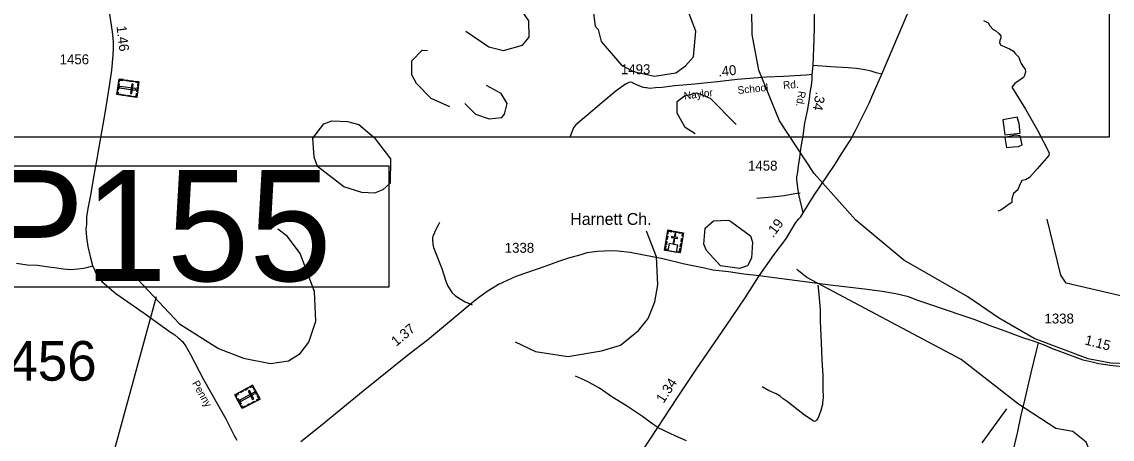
# Model space of a CAD drawing. Extents: x 2093524 to 2270757, y 289120 to 570408.
# Drawn here: x 2149214 to 2162986, y 498150 to 503417 of the extents above; entities that cross this region are included whole.
import ezdxf

# ---------------------------------------------------------------- set-up
doc = ezdxf.new("R2010")
doc.units = 0
for name, color, linetype in [('Exist Cultural Cemetery CELL', 7, 'Continuous'), ('Exist Cultural Church with Cemetery CELL', 7, 'Continuous'), ('Exist Cultural Church with Cemetery Label', 7, 'Continuous'), ('Exist Hydrographic Creek Single Shore', 7, 'Continuous'), ('Exist Hydrographic Lagoon', 7, 'Continuous'), ('Exist Hydrographic Misc Water Feature', 7, 'Continuous'), ('Exist Hydrographic Pond Under 1500 Sq Ft', 7, 'Continuous'), ('Exist Road Non-System Type 51', 7, 'Continuous'), ('Exist Road Primary NC Attributed', 7, 'Continuous'), ('Exist Road Primary NC Mileage Hundredths English Label', 7, 'Continuous'), ('Exist Road Secondary Mileage Hundredths English Label', 7, 'Continuous'), ('Exist Road Secondary Structure Pipe Number Label', 7, 'Continuous'), ('Exist Road Secondary Type 51 Attributed', 7, 'Continuous'), ('Exist Road Secondary Type 51 Label', 7, 'Continuous'), ('Exist Road Secondary Type 51 Number Label', 7, 'Continuous'), ('Map Preparation Inset Cut Line', 7, 'Continuous')]:
    doc.layers.add(name, color=color, linetype=linetype)

msp = doc.modelspace()

# ---------------------------------------------------------------- linework, layer by layer
at = {"layer": 'Exist Cultural Cemetery CELL'}
for points in [[(2150694, 502659), (2150666, 502462), (2150414, 502498), (2150442, 502695)], [(2150437, 502662), (2150449, 502661), (2150452, 502682), (2150492, 502677), (2150493, 502688), (2150442, 502695)], [(2150445, 502636), (2150433, 502552), (2150422, 502554), (2150434, 502638)], [(2150650, 502555), (2150652, 502574), (2150452, 502602), (2150449, 502584)], [(2150511, 502685), (2150554, 502679), (2150552, 502668), (2150510, 502674)], [(2150578, 502676), (2150621, 502670), (2150619, 502658), (2150576, 502664)], [(2150621, 502628), (2150602, 502631), (2150586, 502514), (2150604, 502512)], [(2150651, 502665), (2150650, 502654), (2150681, 502650), (2150676, 502609), (2150687, 502608), (2150694, 502659)], [(2150684, 502586), (2150676, 502535), (2150665, 502536), (2150672, 502587)], [(2150419, 502531), (2150430, 502529), (2150427, 502507), (2150467, 502502), (2150465, 502491), (2150414, 502498)], [(2150487, 502499), (2150530, 502493), (2150528, 502482), (2150485, 502488)], [(2150552, 502490), (2150595, 502484), (2150594, 502472), (2150551, 502478)], [(2150623, 502468), (2150625, 502479), (2150657, 502475), (2150662, 502515), (2150673, 502513), (2150666, 502462)], [(2152129, 498831), (2152224, 498656), (2151999, 498535), (2151905, 498710)], [(2151921, 498681), (2151931, 498687), (2151921, 498706), (2151956, 498725), (2151951, 498735), (2151905, 498710)], [(2151967, 498743), (2152005, 498764), (2152010, 498754), (2151972, 498733)], [(2152155, 498721), (2152146, 498737), (2151968, 498641), (2151977, 498625)], [(2152026, 498775), (2152064, 498796), (2152070, 498786), (2152031, 498765)], [(2152089, 498763), (2152072, 498754), (2152128, 498650), (2152145, 498659)], [(2152091, 498810), (2152097, 498800), (2152125, 498816), (2152144, 498780), (2152154, 498785), (2152129, 498831)], [(2152165, 498766), (2152189, 498720), (2152179, 498715), (2152154, 498760)], [(2152186, 498635), (2152180, 498645), (2152209, 498660), (2152189, 498696), (2152199, 498701), (2152224, 498655)], [(2151943, 498665), (2151983, 498590), (2151973, 498585), (2151932, 498660)], [(2151984, 498564), (2151994, 498570), (2152004, 498550), (2152040, 498569), (2152045, 498560), (2151999, 498535)], [(2152058, 498579), (2152096, 498600), (2152101, 498590), (2152063, 498569)], [(2152116, 498610), (2152154, 498631), (2152159, 498621), (2152121, 498600)]]:
    msp.add_lwpolyline(points, close=True, dxfattribs=at)
at = {"layer": 'Exist Cultural Church with Cemetery CELL'}
for points in [[(2157375, 500787), (2157571, 500754), (2157529, 500503), (2157332, 500536)], [(2157368, 500744), (2157379, 500743), (2157384, 500774), (2157424, 500768), (2157426, 500778), (2157375, 500787)], [(2157448, 500775), (2157499, 500766), (2157497, 500755), (2157446, 500764)], [(2157564, 500711), (2157553, 500713), (2157558, 500745), (2157518, 500751), (2157520, 500762), (2157571, 500754)], [(2157344, 500605), (2157351, 500648), (2157362, 500646), (2157355, 500603)], [(2157355, 500671), (2157362, 500714), (2157374, 500712), (2157366, 500669)], [(2157375, 500529), (2157485, 500510), (2157501, 500599), (2157450, 500608), (2157464, 500688), (2157497, 500683), (2157498, 500694), (2157466, 500699), (2157473, 500741), (2157462, 500743), (2157454, 500701), (2157422, 500707), (2157420, 500696), (2157453, 500690), (2157439, 500610), (2157390, 500618)], [(2157541, 500641), (2157548, 500684), (2157559, 500682), (2157552, 500639)], [(2157365, 500531), (2157367, 500542), (2157345, 500546), (2157352, 500585), (2157341, 500587), (2157332, 500536)], [(2157496, 500508), (2157498, 500520), (2157520, 500516), (2157526, 500556), (2157537, 500554), (2157529, 500503)], [(2157529, 500576), (2157537, 500619), (2157548, 500617), (2157541, 500574)]]:
    msp.add_lwpolyline(points, close=True, dxfattribs=at)
at = {"layer": 'Exist Hydrographic Creek Single Shore'}
msp.add_lwpolyline([(2161363, 503435), (2161419, 503402), (2161442, 503364), (2161482, 503318), (2161516, 503301), (2161553, 503269), (2161582, 503239), (2161582, 503210), (2161566, 503179), (2161563, 503152), (2161582, 503122), (2161592, 503116), (2161630, 503099), (2161689, 503076), (2161739, 503045), (2161756, 503022), (2161807, 502969), (2161823, 502920), (2161836, 502890), (2161867, 502846), (2161886, 502817), (2161890, 502783), (2161878, 502739), (2161868, 502712), (2161756, 502638), (2161717, 502591), (2161768, 502511), (2161892, 502316), (2162043, 502049), (2162192, 501762), (2162187, 501728), (2162038, 501562), (2161944, 501450), (2161892, 501423), (2161846, 501416), (2161812, 501343), (2161793, 501297), (2161739, 501251), (2161717, 501182), (2161717, 501136), (2161686, 501117), (2161637, 501083), (2161579, 501041), (2161544, 501029)], dxfattribs=at)
at = {"layer": 'Exist Hydrographic Lagoon'}
for points in [[(2161605, 502180), (2161630, 501990), (2161824, 502012), (2161810, 502132), (2161785, 502212)], [(2161632, 501956), (2161652, 501830), (2161737, 501839), (2161802, 501844), (2161851, 501864), (2161824, 501978), (2161759, 501986)]]:
    msp.add_lwpolyline(points, close=True, dxfattribs=at)
at = {"layer": 'Exist Hydrographic Misc Water Feature'}
for points in [[(2159750, 500914), (2159221, 501502), (2158785, 502167), (2158523, 502805), (2158437, 503256), (2158435, 503571), (2158492, 503839), (2158599, 504122), (2159038, 504583), (2159328, 504760)], [(2154821, 503299), (2155114, 503103), (2155297, 503054), (2155539, 503121), (2155621, 503221), (2155620, 503431), (2155478, 503631), (2155152, 503729), (2154936, 503717)], [(2154619, 502342), (2154385, 502449), (2154200, 502639), (2154141, 502749), (2154140, 502923), (2154273, 503058), (2154339, 503056)], [(2154810, 502384), (2154944, 502250), (2155119, 502194), (2155277, 502211), (2155310, 502253), (2155343, 502387), (2155267, 502513), (2155083, 502612)], [(2157719, 502001), (2157594, 502082), (2157493, 502265), (2157492, 502409), (2157583, 502483), (2157741, 502519), (2157908, 502453), (2158235, 502122)], [(2164331, 499789), (2164290, 499671), (2164182, 499562), (2164166, 499503), (2163868, 499237), (2163760, 499170), (2163185, 499100), (2162969, 499107), (2162685, 499162), (2162001, 499419), (2161549, 499681), (2161165, 499947), (2160354, 500407), (2159750, 500914)], [(2164331, 499789), (2164106, 499846), (2163564, 499850), (2162405, 500119), (2162338, 500219), (2162165, 500928)], [(2150684, 500161), (2151204, 499606), (2151697, 499294), (2152014, 499170), (2152356, 499104), (2152581, 499139), (2152730, 499231), (2152838, 499373), (2152928, 499640), (2152909, 500015), (2152731, 500491), (2152572, 500707), (2152447, 500798)], [(2155445, 499380), (2155704, 499257), (2156112, 499193), (2156537, 499263), (2156778, 499337), (2157002, 499523), (2157126, 499674), (2157208, 499883), (2157249, 500098), (2157230, 500450), (2157103, 500774)], [(2166845, 492581), (2166777, 492913), (2166625, 493228), (2166550, 493312), (2166516, 493437), (2166465, 493487), (2166465, 493546), (2166297, 493828), (2166280, 493901), (2165549, 495080), (2165112, 495653), (2165103, 495886), (2164985, 495967), (2164769, 496027), (2162759, 497865), (2162658, 498113), (2162490, 498245), (2162274, 498285), (2161805, 498593), (2161078, 499155), (2159131, 500192), (2159005, 500293)], [(2161652, 498531), (2161340, 498105)]]:
    msp.add_lwpolyline(points, dxfattribs=at)
at = {"layer": 'Exist Hydrographic Pond Under 1500 Sq Ft'}
for points in [[(2157207, 502730), (2157473, 502774), (2157598, 502860), (2157697, 502976), (2157729, 503300), (2157619, 503584), (2157401, 503831), (2157158, 503954), (2156917, 503979), (2156667, 503945), (2156526, 503885), (2156451, 503801), (2156419, 503661), (2156454, 503362), (2156496, 503318), (2156530, 503170), (2156790, 502869), (2156940, 502788), (2157207, 502730)], [(2153508, 501262), (2153283, 501336), (2152948, 501592), (2152906, 501707), (2152888, 501947), (2153028, 502131), (2153128, 502166), (2153328, 502158), (2153470, 502119), (2153663, 501955), (2153872, 501688), (2153866, 501380), (2153775, 501296), (2153667, 501253), (2153508, 501262)], [(2157950, 500904), (2158134, 500914), (2158167, 500903), (2158420, 500714), (2158445, 500638), (2158430, 500432), (2158380, 500338), (2158280, 500304), (2158039, 500338), (2157863, 500529), (2157829, 500611), (2157844, 500811), (2157950, 500904)]]:
    msp.add_lwpolyline(points, dxfattribs=at)
at = {"layer": 'Exist Road Non-System Type 51'}
for points in [[(2160075, 502757), (2160006, 502774), (2159942, 502792), (2159864, 502811), (2159758, 502828), (2159652, 502837), (2159434, 502849), (2159209, 502866)], [(2157095, 502584), (2157062, 502589), (2156992, 502619), (2156954, 502636), (2156928, 502648), (2156922, 502652), (2156905, 502654), (2156882, 502649), (2156840, 502629), (2156722, 502544), (2156542, 502393), (2156343, 502227), (2156266, 502164), (2156212, 502118), (2156197, 502097), (2156183, 502077), (2156157, 502017), (2156136, 501955)], [(2159046, 501255), (2158980, 501245), (2158842, 501222), (2158690, 501205), (2158500, 501185)], [(2154488, 500883), (2154473, 500849), (2154433, 500769), (2154421, 500739), (2154407, 500711), (2154402, 500693), (2154400, 500665), (2154406, 500609), (2154416, 500567), (2154518, 500304), (2154569, 500142), (2154597, 500082), (2154613, 500054), (2154631, 500020), (2154649, 499996), (2154690, 499957), (2154752, 499919), (2154814, 499883), (2154904, 499844)], [(2149147, 500370), (2149281, 500351), (2149411, 500345), (2149585, 500320), (2149627, 500316), (2149741, 500299), (2149834, 500293), (2149921, 500298), (2149995, 500306), (2150051, 500320), (2150109, 500337)], [(2159269, 500092), (2159276, 500020), (2159297, 499786), (2159298, 499640), (2159311, 499367), (2159318, 499155), (2159330, 498949), (2159333, 498783), (2159335, 498675), (2159333, 498643), (2159329, 498611), (2159326, 498587), (2159306, 498511), (2159287, 498451), (2159267, 498409), (2159251, 498389), (2159239, 498379), (2159225, 498374), (2159213, 498376), (2159195, 498388), (2159101, 498454), (2158882, 498624), (2158831, 498658), (2158791, 498692), (2158741, 498720), (2158647, 498765), (2158565, 498809)], [(2162052, 499366), (2162025, 499264), (2161957, 498985), (2161881, 498659), (2161832, 498451), (2161789, 498245), (2161734, 498017), (2161699, 497823), (2161678, 497754), (2161668, 497719), (2161642, 497654), (2161605, 497592)], [(2157248, 498295), (2157184, 498339), (2157055, 498434), (2156853, 498569), (2156668, 498686), (2156509, 498793), (2156381, 498866), (2156321, 498896), (2156209, 498943)], [(2157248, 498295), (2157326, 498260), (2157469, 498191), (2157607, 498132)]]:
    msp.add_lwpolyline(points, dxfattribs=at)
at = {"layer": 'Exist Road Primary NC Attributed'}
for points in [[(2159083, 501004), (2159214, 501216), (2159392, 501477), (2159488, 501620), (2159568, 501752), (2159675, 501920), (2159739, 502037), (2159790, 502138), (2159838, 502231), (2159916, 502392), (2159963, 502498), (2160075, 502757), (2160279, 503233), (2160439, 503605)], [(2158526, 500212), (2158719, 500482), (2158864, 500675), (2158991, 500883), (2159023, 500925), (2159052, 500955), (2159083, 501004)], [(2156354, 493792), (2156349, 494232), (2156341, 495639), (2156337, 496107), (2156345, 496477), (2156332, 496567), (2156355, 496689), (2156375, 496835), (2156384, 496887), (2156404, 496943), (2156442, 497055), (2156469, 497113), (2156489, 497149), (2156506, 497176), (2156570, 497272), (2156826, 497653), (2157133, 498125), (2157248, 498295), (2157488, 498661), (2157732, 499028), (2158109, 499582), (2158352, 499934), (2158526, 500212)]]:
    msp.add_lwpolyline(points, dxfattribs=at)
at = {"layer": 'Exist Road Secondary Structure Pipe Number Label'}
msp.add_line((2150913, 499946), (2150079, 496907), dxfattribs=at)
msp.add_lwpolyline([(2148784, 501601), (2153849, 501601), (2153849, 500066), (2148784, 500066)], close=True, dxfattribs=at)
at = {"layer": 'Exist Road Secondary Type 51 Attributed'}
for points in [[(2150312, 503568), (2150355, 503290), (2150363, 503212), (2150370, 503160), (2150370, 503084), (2150363, 502994), (2150345, 502806), (2150320, 502633), (2150261, 502263), (2150187, 501836), (2150163, 501688), (2150121, 501455), (2150084, 501251), (2150052, 501082), (2150031, 500958), (2150030, 500860), (2150024, 500808), (2150025, 500750), (2150031, 500696), (2150050, 500580), (2150078, 500457), (2150103, 500359), (2150109, 500337), (2150127, 500299), (2150139, 500265), (2150149, 500245), (2150176, 500203), (2150192, 500182), (2150230, 500137), (2150403, 499987), (2150758, 499739), (2151093, 499501), (2151148, 499465), (2151190, 499427), (2151210, 499411), (2151226, 499395), (2151244, 499382), (2151262, 499356), (2151284, 499324), (2151343, 499220), (2151509, 498903), (2151793, 498407), (2151897, 498198), (2151930, 498138)], [(2159199, 502750), (2159209, 502866), (2159216, 503084), (2159225, 503332), (2159228, 503512)], [(2159199, 502750), (2159123, 502745), (2158833, 502726), (2158621, 502717), (2158251, 502687), (2158003, 502661), (2157670, 502626), (2157460, 502609), (2157302, 502589), (2157218, 502582), (2157146, 502576), (2157108, 502582), (2157095, 502584)], [(2159083, 501004), (2159028, 501237), (2159015, 501323), (2159003, 501425), (2159002, 501462), (2159015, 501518), (2159021, 501564), (2159030, 501623), (2159040, 501706), (2159058, 501840), (2159083, 501978), (2159106, 502136), (2159142, 502315), (2159165, 502443), (2159172, 502523), (2159190, 502611), (2159195, 502689), (2159199, 502750)], [(2158526, 500212), (2158335, 500230), (2158139, 500260), (2157944, 500284), (2157838, 500306), (2157585, 500357), (2157312, 500427), (2157072, 500470), (2156898, 500506), (2156744, 500522), (2156635, 500527), (2156571, 500521), (2156486, 500518), (2156352, 500503), (2156277, 500477), (2156119, 500435), (2155992, 500393), (2155832, 500334), (2155456, 500202), (2155235, 500100), (2155078, 500003), (2154949, 499907), (2154877, 499850), (2154589, 499608), (2154339, 499401), (2154107, 499223), (2153527, 498755), (2152985, 498313), (2152740, 498117)], [(2163116, 499064), (2162958, 499081), (2162906, 499087), (2162818, 499102), (2162735, 499122), (2162621, 499147), (2162517, 499186), (2162225, 499293), (2162139, 499330), (2162052, 499366), (2161994, 499386), (2161870, 499425), (2161634, 499512), (2161457, 499574), (2161243, 499659), (2161091, 499710), (2160671, 499852), (2160533, 499901), (2160412, 499945), (2160253, 499983), (2160082, 500014), (2159857, 500041), (2159426, 500094), (2159105, 500135), (2158718, 500185), (2158526, 500212)]]:
    msp.add_lwpolyline(points, dxfattribs=at)
at = {"layer": 'Map Preparation Inset Cut Line'}
msp.add_lwpolyline([(2134776, 516144), (2162949, 516144), (2162949, 501961), (2134776, 501961)], close=True, dxfattribs=at)

# ---------------------------------------------------------------- texts
at = {"layer": 'Exist Cultural Church with Cemetery Label'}
msp.add_text('Harnett Ch.', height=150, dxfattribs=at).set_placement((2156142, 500854))
at = {"layer": 'Exist Road Primary NC Mileage Hundredths English Label'}
for s, rotation, p in [('.19', 53.0854, (2158704, 500686)), ('1.34', 56.901, (2157320, 498595))]:
    msp.add_text(s, height=125, rotation=rotation, dxfattribs=at).set_placement(p)
at = {"layer": 'Exist Road Secondary Mileage Hundredths English Label'}
for s, rotation, p in [('1.46', 276.8277, (2150409, 503361)), ('.40', 5.9556, (2158014, 502725)), ('.34', 259.3957, (2159245, 502538)), ('1.37', 39.6233, (2153944, 499315)), ('1.15', 345.5479, (2162632, 499347))]:
    msp.add_text(s, height=125, rotation=rotation, dxfattribs=at).set_placement(p)
at = {"layer": 'Exist Road Secondary Structure Pipe Number Label'}
msp.add_text('P155', height=1400, dxfattribs=at).set_placement((2148756, 500145))
at = {"layer": 'Exist Road Secondary Type 51 Label'}
for s, rotation, p in [('Naylor', 7.0469, (2157582, 502435)), ('School', 5.9556, (2158260, 502505)), ('Rd.', 3.645, (2158832, 502570)), ('Rd.', 260.1141, (2159025, 502549)), ('Penny', 299.4507, (2151362, 498857))]:
    msp.add_text(s, height=95, rotation=rotation, dxfattribs=at).set_placement(p)
at = {"layer": 'Exist Road Secondary Type 51 Number Label'}
for s, height, p in [('1456', 125, (2149692, 502881)), ('1493', 125, (2156781, 502756)), ('1458', 125, (2158387, 501539)), ('1338', 125, (2155314, 500502)), ('1338', 125, (2162131, 499610)), ('1456', 500, (2148672, 498888))]:
    msp.add_text(s, height=height, dxfattribs=at).set_placement(p)

doc.saveas('drawing.dxf')
